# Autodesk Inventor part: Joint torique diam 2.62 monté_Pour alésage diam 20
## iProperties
Shininess: 64.0
Length Units: 11269
Angle Units: 11279
Time Units: 11290
Mass Units: 11283
Length Display Precision: 3
Angle Display Precision: 2
Compacted: True
Part Number: Joint torique diam 2.62 monté_Pour alésage diam 20
Document SubType Name: Modeling
Created: 2006-01
Material: Par défaut
Designer: riri
Density: 0.0
Volumn: 0.0
Area: 0.0
PropertySet Name: Model Information
Control State: 0
Master: False
Checked Out: False
Author: riri
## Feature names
1. Base1
